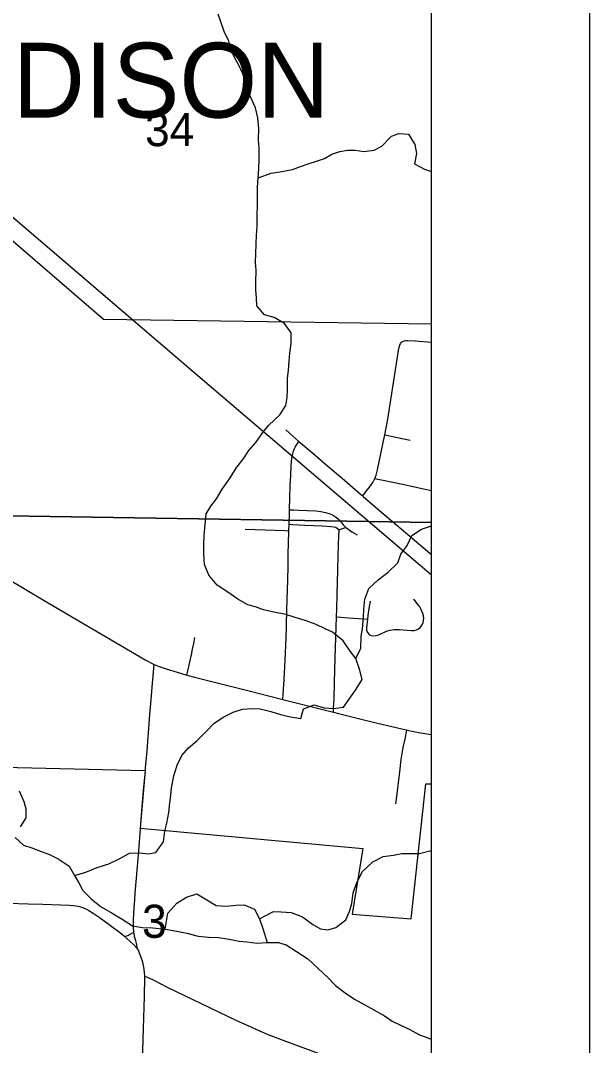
# Model space of a CAD drawing. Extents: x 0 to 34, y 0 to 22.
# Drawn here: x 8.28 to 9, y 14.663 to 15.96 of the extents above; entities that cross this region are included whole.
import ezdxf

# ---------------------------------------------------------------- set-up
doc = ezdxf.new("R2010")
doc.units = 0
for name, color, linetype in [('Default', 7, 'Continuous'), ('GM_X_Corporation', 7, 'Continuous'), ('GM_X_County_Road', 7, 'Continuous'), ('GM_X_Interchange_Ramps', 7, 'Continuous'), ('GM_X_Major_River_Text', 7, 'Continuous'), ('GM_X_Section', 7, 'Continuous'), ('GM_X_Section_Text', 7, 'Continuous'), ('GM_X_Unincorporated', 7, 'Continuous'), ('GM_X_US_Location', 7, 'Continuous'), ('SH_Cut_Line', 7, 'Continuous'), ('SH_Text', 7, 'Continuous')]:
    doc.layers.add(name, color=color, linetype=linetype)

msp = doc.modelspace()

# ---------------------------------------------------------------- linework, layer by layer
at = {"layer": 'Default'}
for points in [[(8.8, 14), (8.8, 18.8069)], [(8.1681, 15.0172), (8.4377, 15.0106), (8.4314, 14.9376), (8.7131, 14.9122), (8.6996, 14.8288), (8.7742, 14.8231), (8.7927, 14.9939), (8.8, 14.9937), (8.8, 15.5756), (8.385, 15.5812), (8.2421, 15.7041)]]:
    msp.add_lwpolyline(points, dxfattribs=at)
for points in [[(8.8, 15.3246), (8.8, 16.334), (7.9948, 16.3527), (7.9737, 15.6015), (7.9679, 15.3374)], [(8.8, 14.3281), (8.8, 15.3246), (7.9679, 15.3374), (7.9551, 14.5952), (7.9448, 14.3373)]]:
    msp.add_lwpolyline(points, close=True, dxfattribs=at)
at = {"layer": 'GM_X_Corporation'}
msp.add_lwpolyline([(8.0101, 16.0566), (8.0064, 16.0438), (8.0032, 16.0324), (8.0011, 16.0214), (8, 16.0122), (7.9995, 15.9972), (8, 15.9869), (8.0018, 15.9759), (8.0044, 15.965), (8.008, 15.9554), (8.0122, 15.9455), (8.0171, 15.9362), (8.0217, 15.929), (8.0261, 15.9226), (8.0314, 15.9163), (8.0364, 15.9108), (8.0427, 15.9049), (8.0587, 15.8914), (8.5043, 15.5105), (8.8, 15.2581)], dxfattribs=at)
at = {"layer": 'GM_X_County_Road'}
msp.add_lwpolyline([(8.2349, 15.2701), (8.2857, 15.2401), (8.3098, 15.2259), (8.3579, 15.1975), (8.3875, 15.1804), (8.4384, 15.1505), (8.4448, 15.1471), (8.449, 15.145), (8.4553, 15.1425), (8.4641, 15.1393), (8.4783, 15.1351), (8.4905, 15.1315), (8.4999, 15.1289), (8.5692, 15.1116), (8.6083, 15.1014), (8.6119, 15.1005), (8.6475, 15.0918), (8.6758, 15.0845), (8.6825, 15.0828), (8.7077, 15.0764), (8.7317, 15.0704), (8.768, 15.0621), (8.7688, 15.0619), (8.7778, 15.06), (8.7863, 15.0584), (8.8, 15.0563)], dxfattribs=at)
at = {"layer": 'GM_X_Interchange_Ramps'}
for points in [[(8.4379, 15.01), (8.4382, 15.0139), (8.44, 15.0354), (8.4436, 15.0816), (8.4453, 15.1003), (8.4471, 15.1214), (8.4482, 15.1351), (8.449, 15.145)], [(8.4316, 14.937), (8.433, 14.9544), (8.4356, 14.9856), (8.4367, 14.998), (8.4379, 15.01)], [(8.4233, 14.8062), (8.4231, 14.8077), (8.4228, 14.8117), (8.4229, 14.8232), (8.4232, 14.8286), (8.4238, 14.8375), (8.4244, 14.8469), (8.425, 14.8556), (8.4259, 14.8653), (8.4267, 14.8744), (8.4297, 14.9089), (8.4316, 14.937)], [(8.2646, 14.8428), (8.2895, 14.8421), (8.3081, 14.8414), (8.3305, 14.8409), (8.3414, 14.8403), (8.3467, 14.84), (8.3529, 14.8389), (8.3587, 14.8372), (8.3632, 14.8353), (8.3664, 14.8337), (8.3717, 14.8302), (8.3794, 14.825), (8.3921, 14.8159), (8.407, 14.8047), (8.412, 14.8007)], [(8.412, 14.8007), (8.4156, 14.802), (8.4179, 14.8031), (8.4195, 14.8041), (8.4223, 14.8057), (8.4233, 14.8062)], [(8.412, 14.8007), (8.4141, 14.7987), (8.4234, 14.79), (8.4281, 14.7851)], [(8.4281, 14.7851), (8.4265, 14.7917), (8.4256, 14.7953), (8.4246, 14.7989), (8.4235, 14.8043), (8.4233, 14.8062)], [(8.4371, 14.7506), (8.4368, 14.7557), (8.4359, 14.762), (8.4345, 14.7681), (8.4327, 14.7741), (8.4306, 14.7796), (8.429, 14.7835), (8.4281, 14.7851)], [(8.4106, 14), (8.4118, 14.026), (8.4139, 14.0601), (8.4151, 14.088), (8.416, 14.1129), (8.4165, 14.1284), (8.4182, 14.1656), (8.4193, 14.1904), (8.4206, 14.2277), (8.423, 14.2805), (8.424, 14.3053), (8.425, 14.3426), (8.4263, 14.3829), (8.4277, 14.4233), (8.4288, 14.4544), (8.4297, 14.4854), (8.4301, 14.5041), (8.4313, 14.5444), (8.4325, 14.5848), (8.434, 14.6283), (8.4357, 14.6842), (8.4369, 14.7246), (8.4372, 14.7495), (8.4371, 14.7506)], [(8.4371, 14.7506), (8.4412, 14.7487), (8.447, 14.7461), (8.4665, 14.7363), (8.5084, 14.7161), (8.5532, 14.6945), (8.5715, 14.6862), (8.5787, 14.683), (8.5922, 14.6773), (8.5987, 14.6745), (8.6132, 14.6689), (8.6599, 14.652), (8.6832, 14.6434), (8.7064, 14.6346), (8.7238, 14.6277), (8.765, 14.6115), (8.7894, 14.6019), (8.8, 14.5979)]]:
    msp.add_lwpolyline(points, dxfattribs=at)
at = {"layer": 'GM_X_Section'}
for points in [[(8.5807, 15.7608), (8.5815, 15.7721), (8.5819, 15.7847), (8.5819, 15.7984), (8.5811, 15.8086), (8.5815, 15.8231), (8.5804, 15.8367), (8.5773, 15.8493), (8.5712, 15.8622), (8.5671, 15.8725), (8.5652, 15.8827), (8.561, 15.893), (8.556, 15.9032), (8.5507, 15.9127), (8.5462, 15.9234), (8.5435, 15.9336), (8.5378, 15.9458), (8.5332, 15.958), (8.5302, 15.9675)], [(8.5807, 15.7608), (8.5971, 15.7664), (8.6108, 15.7687), (8.6241, 15.771), (8.6344, 15.7748), (8.6439, 15.7782), (8.6545, 15.7816), (8.6644, 15.785), (8.6739, 15.7904), (8.6842, 15.7938), (8.6937, 15.7957), (8.7036, 15.7957), (8.7142, 15.7941), (8.7276, 15.7957), (8.7371, 15.8006), (8.7493, 15.8135), (8.7588, 15.8169), (8.7709, 15.8158), (8.7789, 15.8029), (8.7812, 15.7915), (8.7785, 15.7782), (8.7911, 15.7717), (8.8, 15.7685)], [(8.3483, 14.8779), (8.3624, 14.882), (8.3768, 14.8881), (8.3917, 14.8927), (8.4054, 14.8995), (8.4179, 14.9063), (8.4308, 14.9067), (8.4415, 14.9052), (8.451, 14.9071), (8.4609, 14.9204), (8.4624, 14.9341), (8.4651, 14.9439), (8.4674, 14.9576), (8.4689, 14.9698), (8.4701, 14.9793), (8.4708, 14.9888), (8.4739, 15.004), (8.4781, 15.0176), (8.4842, 15.0298), (8.4925, 15.0393), (8.5032, 15.0484), (8.515, 15.0602), (8.5249, 15.0704), (8.5371, 15.0788), (8.5489, 15.0845), (8.561, 15.0883), (8.5732, 15.089), (8.5831, 15.0886), (8.5968, 15.0852), (8.6089, 15.0814), (8.6215, 15.0788), (8.6348, 15.0765), (8.6379, 15.0886), (8.6516, 15.0939), (8.6641, 15.0901), (8.6759, 15.089), (8.6888, 15.0909), (8.6957, 15.1011), (8.7048, 15.1137), (8.7124, 15.1258), (8.709, 15.1388), (8.7041, 15.1524), (8.6972, 15.1619), (8.6881, 15.1749), (8.6748, 15.1859), (8.6653, 15.1901), (8.6539, 15.1954), (8.6402, 15.2007), (8.6273, 15.2041), (8.6155, 15.2083), (8.6006, 15.211), (8.5873, 15.214), (8.5774, 15.2178), (8.5676, 15.2205), (8.555, 15.2273), (8.5421, 15.2365), (8.5288, 15.2452), (8.5181, 15.2577), (8.5128, 15.2714), (8.512, 15.2847), (8.5117, 15.2973), (8.5124, 15.3083), (8.5147, 15.3356), (8.5208, 15.3451), (8.5277, 15.3546), (8.5349, 15.3668), (8.5444, 15.3797), (8.5536, 15.3945), (8.5615, 15.4048), (8.5688, 15.4158), (8.5775, 15.4256), (8.5867, 15.4382), (8.5943, 15.4477), (8.608, 15.4606), (8.6156, 15.4727), (8.6175, 15.4826), (8.6179, 15.4925), (8.6179, 15.5066), (8.619, 15.5172), (8.6198, 15.5286), (8.6206, 15.5389), (8.6225, 15.551), (8.6225, 15.5643), (8.6141, 15.5761), (8.6008, 15.5841), (8.5886, 15.5871), (8.5791, 15.5985), (8.5784, 15.6084), (8.5776, 15.6187), (8.5776, 15.6285), (8.578, 15.6434), (8.5772, 15.654), (8.5776, 15.6639), (8.578, 15.6775), (8.5784, 15.6878), (8.5792, 15.6996), (8.5792, 15.7133), (8.5796, 15.7262), (8.5796, 15.7387), (8.58, 15.7482), (8.5807, 15.7608)], [(8.7041, 15.1524), (8.7106, 15.1653), (8.7109, 15.1805), (8.7128, 15.19), (8.714, 15.2049), (8.7144, 15.2147), (8.7155, 15.2273), (8.7209, 15.2409), (8.7327, 15.252), (8.7452, 15.2618), (8.7574, 15.2736), (8.7612, 15.2846), (8.7692, 15.2956), (8.7753, 15.3082), (8.7875, 15.3161), (8.7973, 15.3196), (8.8, 15.3203)], [(8.5822, 14.8231), (8.6001, 14.8322), (8.6096, 14.8318), (8.6225, 14.831), (8.6366, 14.8257), (8.6499, 14.8158), (8.6594, 14.8105), (8.6689, 14.809), (8.6788, 14.812), (8.6914, 14.8219), (8.6963, 14.8325), (8.699, 14.8424), (8.7009, 14.8561), (8.7058, 14.8698), (8.7127, 14.8831), (8.7256, 14.8952), (8.739, 14.9017), (8.7519, 14.9036), (8.7625, 14.9058), (8.7747, 14.9055), (8.785, 14.9058), (8.7979, 14.9089), (8.8, 14.9089)], [(8.4631, 14.8098), (8.4662, 14.83), (8.4776, 14.8429), (8.4898, 14.8505), (8.5031, 14.8546), (8.5156, 14.847), (8.5274, 14.8398), (8.54, 14.8391), (8.5529, 14.8402), (8.5628, 14.8406), (8.5761, 14.8352), (8.5822, 14.8231), (8.5864, 14.8109), (8.5921, 14.7931)]]:
    msp.add_lwpolyline(points, dxfattribs=at)
at = {"layer": 'GM_X_Section_Text'}
for points in [[(8.278, 14.985), (8.284, 14.9717), (8.2867, 14.9622), (8.2867, 14.9508), (8.2795, 14.9394)], [(8.273, 14.9258), (8.2836, 14.9163), (8.2943, 14.9128), (8.3072, 14.9079), (8.3167, 14.9045), (8.3285, 14.8984), (8.3414, 14.8897), (8.3483, 14.8779), (8.3536, 14.8684), (8.3586, 14.8589), (8.3696, 14.8479), (8.3821, 14.8383), (8.3958, 14.83), (8.4087, 14.8228), (8.4217, 14.814), (8.4342, 14.8121), (8.4472, 14.8117), (8.4631, 14.8098), (8.4776, 14.8075), (8.4905, 14.8049), (8.5046, 14.8011), (8.5179, 14.7999), (8.5305, 14.7995), (8.5438, 14.7973), (8.5567, 14.7946), (8.5662, 14.7938), (8.5788, 14.7923), (8.5921, 14.7931), (8.6065, 14.7931), (8.616, 14.79), (8.6293, 14.7817), (8.6434, 14.7725), (8.6693, 14.7482), (8.6784, 14.7387), (8.6906, 14.7296), (8.7027, 14.7212), (8.7157, 14.7144), (8.7271, 14.7079), (8.7404, 14.7003), (8.7503, 14.6935), (8.7598, 14.6889), (8.7719, 14.6836), (8.7849, 14.6764), (8.8, 14.6709)]]:
    msp.add_lwpolyline(points, dxfattribs=at)
at = {"layer": 'GM_X_US_Location'}
for points in [[(8.7129, 15.3581), (8.7178, 15.3644), (8.7215, 15.3691), (8.7258, 15.3753), (8.7279, 15.3792), (8.7283, 15.3803), (8.7299, 15.3846), (8.7316, 15.3912), (8.7407, 15.4337), (8.741, 15.4354), (8.7446, 15.4551), (8.7528, 15.5067), (8.7584, 15.5422), (8.7595, 15.5476), (8.76, 15.549), (8.7608, 15.5511), (8.7619, 15.5528)], [(8.7619, 15.5528), (8.7637, 15.5537), (8.7653, 15.5543), (8.7674, 15.5546), (8.7698, 15.5546), (8.7793, 15.5542), (8.8, 15.5528)], [(8.6157, 15.4416), (8.6245, 15.4339), (8.6323, 15.4271), (8.6399, 15.4207), (8.6524, 15.41), (8.669, 15.3958), (8.6869, 15.3805), (8.7102, 15.3605), (8.7129, 15.3581), (8.7136, 15.3575), (8.7317, 15.342), (8.7673, 15.3118), (8.7981, 15.2855), (8.8, 15.2839)], [(8.741, 15.4354), (8.7467, 15.4342), (8.7729, 15.4286)], [(8.6119, 15.1005), (8.6124, 15.1074), (8.6129, 15.1135), (8.6136, 15.1259), (8.6149, 15.1505), (8.6152, 15.1598), (8.6156, 15.169), (8.6164, 15.1904), (8.6165, 15.1964), (8.6166, 15.1995), (8.6169, 15.2085), (8.617, 15.2147), (8.6171, 15.2181), (8.6172, 15.2226), (8.6174, 15.2283), (8.6176, 15.238), (8.6185, 15.2682), (8.6187, 15.2788), (8.6188, 15.2865), (8.619, 15.2964), (8.6192, 15.304), (8.6193, 15.3078), (8.6194, 15.3141), (8.6197, 15.3223), (8.6201, 15.3356), (8.6202, 15.3407), (8.6202, 15.342), (8.6206, 15.3548), (8.6209, 15.3607), (8.6211, 15.3659), (8.6212, 15.3689), (8.6212, 15.3715), (8.6218, 15.3838), (8.6223, 15.3963), (8.6227, 15.4016), (8.6231, 15.4054), (8.6236, 15.4085), (8.6244, 15.4115), (8.6253, 15.4146), (8.6264, 15.4174), (8.6276, 15.4199), (8.6296, 15.4233), (8.6323, 15.4271)], [(8.7283, 15.3803), (8.734, 15.3791), (8.7389, 15.378), (8.7633, 15.3728), (8.7918, 15.3666), (8.8, 15.3652)], [(8.6202, 15.3407), (8.6257, 15.3404), (8.6318, 15.34), (8.6536, 15.3391), (8.6598, 15.3385), (8.6659, 15.3373), (8.6689, 15.3365), (8.6718, 15.3354), (8.6746, 15.3341), (8.6773, 15.3325), (8.6798, 15.3307), (8.6822, 15.3287), (8.6844, 15.3265), (8.6883, 15.3217), (8.6905, 15.3195), (8.6918, 15.3183)], [(8.6197, 15.3223), (8.6245, 15.3221), (8.6397, 15.3212), (8.6615, 15.3201), (8.6676, 15.3199), (8.6728, 15.3195), (8.6764, 15.3191), (8.6786, 15.3184), (8.6807, 15.3173), (8.6831, 15.3154)], [(8.6831, 15.3154), (8.6885, 15.3173), (8.6918, 15.3183)], [(8.6918, 15.3183), (8.6928, 15.3174), (8.6958, 15.3151), (8.6993, 15.3127), (8.703, 15.3104), (8.7058, 15.309)], [(8.564, 15.3162), (8.6149, 15.3143), (8.6194, 15.3141)], [(8.6758, 15.0845), (8.6761, 15.0894), (8.6767, 15.1015), (8.6771, 15.1222), (8.6782, 15.153), (8.6798, 15.205), (8.6801, 15.2148), (8.6806, 15.2333), (8.6816, 15.2641), (8.682, 15.2826), (8.6828, 15.3081), (8.6831, 15.3154)], [(8.7189, 15.2024), (8.7176, 15.1912), (8.7178, 15.1881), (8.719, 15.1853), (8.721, 15.183), (8.7238, 15.1816), (8.7268, 15.1812), (8.7299, 15.1816), (8.7329, 15.1824), (8.7358, 15.1835), (8.7413, 15.1863), (8.7442, 15.1873), (8.7472, 15.1882), (8.7502, 15.1887), (8.7533, 15.189), (8.7564, 15.1891), (8.7595, 15.189), (8.7687, 15.1881), (8.7749, 15.1877), (8.778, 15.188), (8.781, 15.1887), (8.7837, 15.1901), (8.7861, 15.1921), (8.7879, 15.1945), (8.7893, 15.1974), (8.79, 15.2004), (8.7902, 15.2034), (8.7898, 15.2065), (8.789, 15.2095), (8.7879, 15.2124), (8.7866, 15.2152), (8.7851, 15.2179), (8.7833, 15.2205), (8.7778, 15.2274)], [(8.7223, 15.2249), (8.7206, 15.2157), (8.7194, 15.2067), (8.7189, 15.2024)], [(8.6798, 15.205), (8.6851, 15.2046), (8.6949, 15.2038), (8.7144, 15.2026), (8.7189, 15.2024)], [(8.4905, 15.1315), (8.4917, 15.1367), (8.4962, 15.157), (8.4977, 15.1642), (8.4992, 15.1716), (8.5004, 15.179)], [(8.755, 14.9687), (8.7563, 14.978), (8.7598, 15.009), (8.7617, 15.0245), (8.7643, 15.0399), (8.7669, 15.0525), (8.7684, 15.0599), (8.7688, 15.0619)]]:
    msp.add_lwpolyline(points, dxfattribs=at)
at = {"layer": 'SH_Cut_Line'}
msp.add_line((9, 21), (9, 14), dxfattribs=at)
at = {"layer": 'SH_Text'}
msp.add_lwpolyline([(2.9377, 14), (8.8, 14), (8.8, 20.8), (2.9842, 20.8), (2.984, 20.7397), (2.9904, 20.3395), (2.9796, 19.7242), (2.9753, 18.7199), (2.9708, 17.6769), (2.9623, 15.7101), (2.9479, 14.7065)], close=True, dxfattribs=at)

# ---------------------------------------------------------------- texts
at = {"layer": 'GM_X_Major_River_Text'}
for s, height, p in [('34', 0.04186, (8.4375, 15.8007)), ('3', 0.0419, (8.4337, 14.799))]:
    msp.add_text(s, height=height, rotation=0, dxfattribs=at).set_placement(p)
at = {"layer": 'GM_X_Unincorporated'}
msp.add_text('EDISON', height=0.0947, rotation=0, dxfattribs=at).set_placement((8.1854, 15.8368))

doc.saveas('drawing.dxf')
